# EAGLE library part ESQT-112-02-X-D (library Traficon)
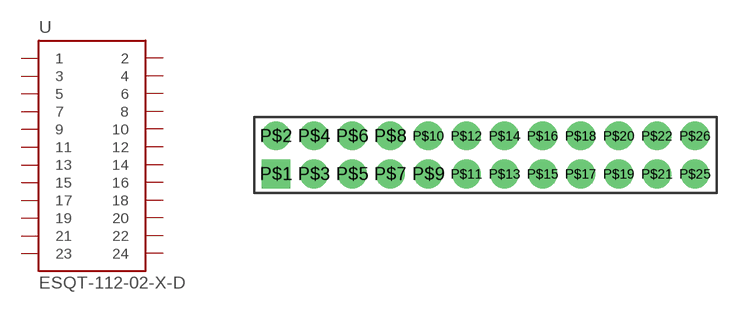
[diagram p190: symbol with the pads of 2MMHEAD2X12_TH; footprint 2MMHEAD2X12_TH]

Designator prefix -

## ESQT-112-02-X-D  [2MMHEAD2X12_TH]
P$1  1  pas
P$2  2  pas
P$3  3  pas
P$4  4  pas
P$5  5  pas
P$6  6  pas
P$7  7  pas
P$8  8  pas
P$9  9  pas
P$10  10  pas
P$11  11  pas
P$12  12  pas
P$13  13  pas
P$14  14  pas
P$15  15  pas
P$16  16  pas
P$17  17
P$18  18
P$19  19
P$20  20
P$21  21
P$22  22
P$25  23
P$26  24

## Footprint 2MMHEAD2X12_TH (pad centres in mm)
drill 1 square: P$1 -11,-1
drill 1 round: P$2 -11,1; P$3 -9,-1; P$4 -9,1; P$5 -7,-1; P$6 -7,1; P$7 -5,-1; P$8 -5,1; P$9 -3,-1; P$10 -3,1; P$11 -1,-1; P$12 -1,1; P$13 1,-1; P$14 1,1; P$15 3,-1; P$16 3,1; P$17 5,-1; P$18 5,1; P$19 7,-1; P$20 7,1; P$21 9,-1; P$22 9,1; P$25 11,-1; P$26 11,1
